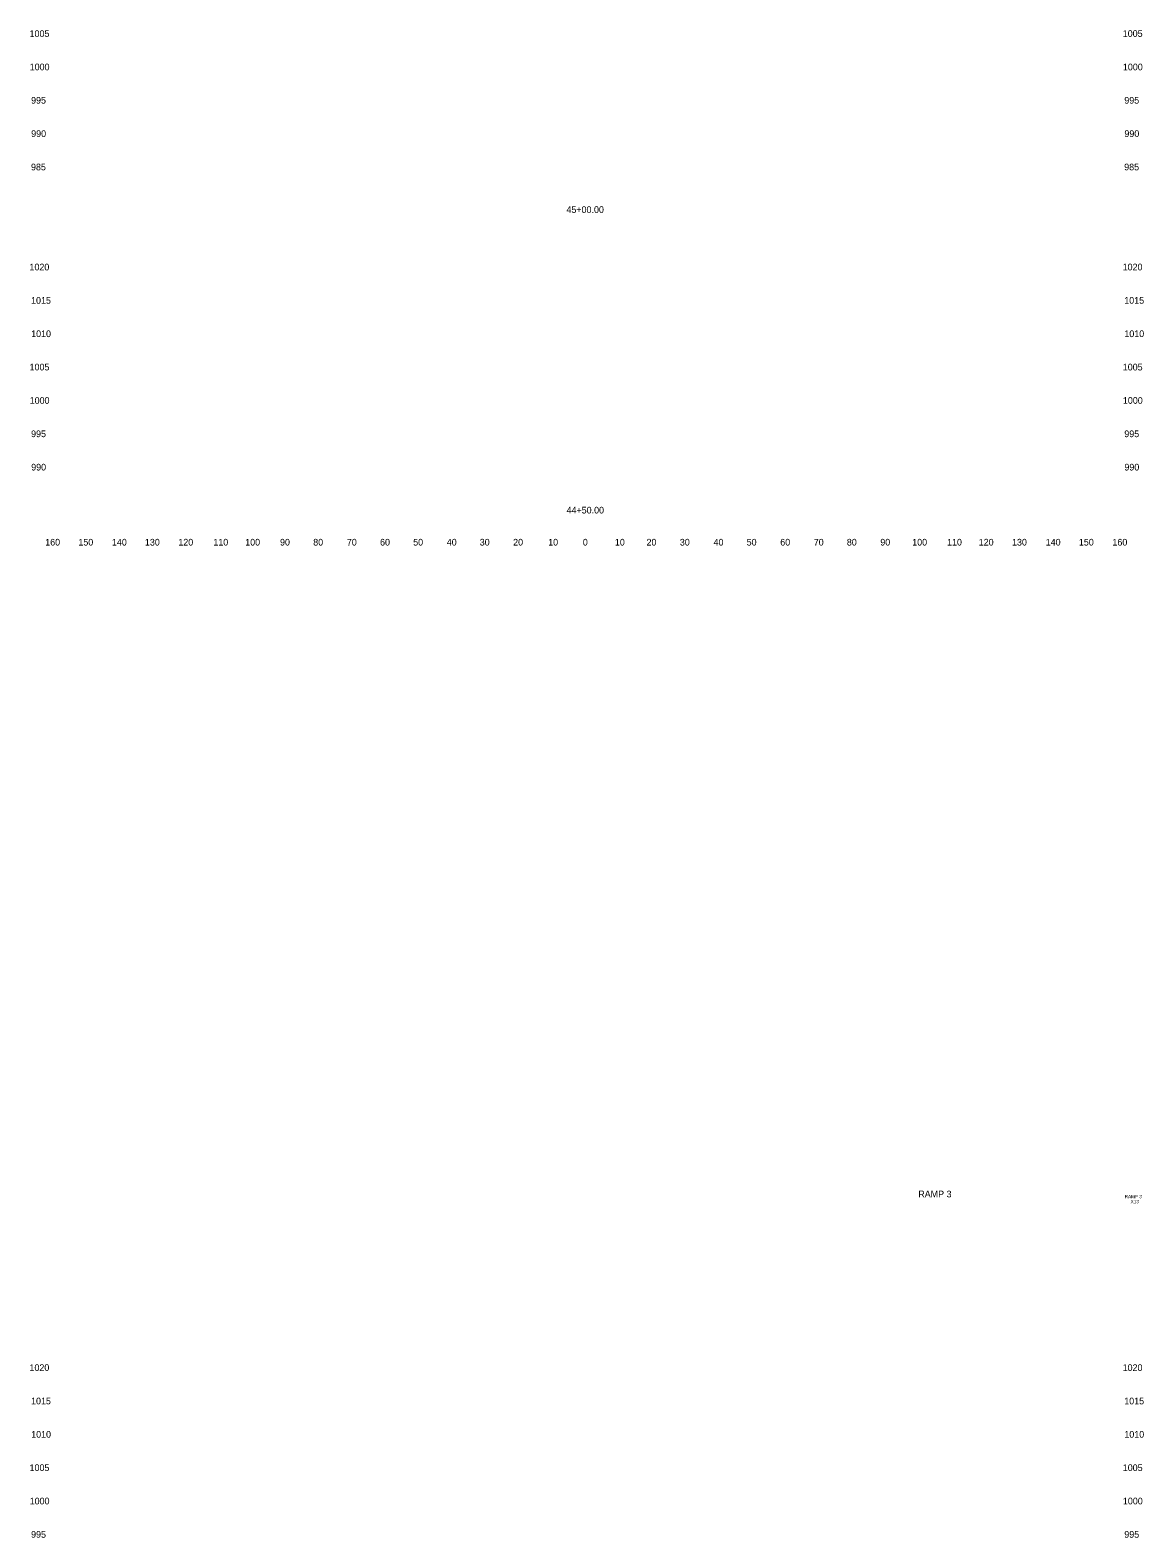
# Model space of a CAD drawing. Extents: x 4994 to 5843, y 4997 to 8804.
# Drawn here: x 5508.6 to 5842.5, y 5900 to 6352 of the extents above; entities that cross this region are included whole.
import ezdxf

# ---------------------------------------------------------------- set-up
doc = ezdxf.new("R2010")
doc.units = 0
for name, color, linetype in [('RD_SHT_ID', 7, 'Continuous'), ('RD_XS_TX_Offset', 7, 'Continuous'), ('RD_XS_TX_Station', 7, 'Continuous')]:
    doc.layers.add(name, color=color, linetype=linetype)

msp = doc.modelspace()

# ---------------------------------------------------------------- texts
at = {"layer": 'RD_SHT_ID'}
for s, height, p in [('RAMP 3', 2, (5774.89, 6002.06)), ('RAMP 3', 1, (5836.78, 6001.8)), ('X13', 1, (5838.57, 6000.3))]:
    msp.add_text(s, height=height, dxfattribs=at).set_placement(p)
at = {"layer": 'RD_XS_TX_Offset'}
for s, p in [('1005', (5508.4, 6350)), ('1005', (5836.2, 6350)), ('1000', (5508.44, 6340)), ('1000', (5836.24, 6340)), ('995', (5508.86, 6330)), ('995', (5836.66, 6330)), ('990', (5508.89, 6320)), ('990', (5836.69, 6320)), ('985', (5508.83, 6310)), ('985', (5836.63, 6310)), ('1020', (5508.37, 6280)), ('1020', (5836.17, 6280)), ('1015', (5508.85, 6270)), ('1015', (5836.65, 6270)), ('1010', (5508.88, 6260)), ('1010', (5836.68, 6260)), ('1005', (5508.4, 6250)), ('1005', (5836.2, 6250)), ('1000', (5508.44, 6240)), ('1000', (5836.24, 6240)), ('995', (5508.86, 6230)), ('995', (5836.66, 6230)), ('990', (5508.89, 6220)), ('990', (5836.69, 6220)), ('160', (5513.1, 6197.5)), ('150', (5523.04, 6197.5)), ('140', (5533.1, 6197.5)), ('130', (5542.99, 6197.5)), ('120', (5553.01, 6197.5)), ('110', (5563.51, 6197.5)), ('100', (5573.07, 6197.5)), ('90', (5583.5, 6197.5)), ('80', (5593.46, 6197.5)), ('70', (5603.54, 6197.5)), ('60', (5613.5, 6197.5)), ('50', (5623.43, 6197.5)), ('40', (5633.5, 6197.5)), ('30', (5643.39, 6197.5)), ('20', (5653.4, 6197.5)), ('10', (5663.91, 6197.5)), ('0', (5674.3, 6197.5)), ('0', (5674.3, 6197.5)), ('10', (5683.91, 6197.5)), ('20', (5693.4, 6197.5)), ('30', (5703.39, 6197.5)), ('40', (5713.5, 6197.5)), ('50', (5723.43, 6197.5)), ('60', (5733.5, 6197.5)), ('70', (5743.54, 6197.5)), ('80', (5753.46, 6197.5)), ('90', (5763.5, 6197.5)), ('100', (5773.07, 6197.5)), ('110', (5783.51, 6197.5)), ('120', (5793.01, 6197.5)), ('130', (5802.99, 6197.5)), ('140', (5813.1, 6197.5)), ('150', (5823.04, 6197.5)), ('160', (5833.1, 6197.5)), ('1020', (5508.37, 5950)), ('1020', (5836.17, 5950)), ('1015', (5508.85, 5940)), ('1015', (5836.65, 5940)), ('1010', (5508.88, 5930)), ('1010', (5836.68, 5930)), ('1005', (5508.4, 5920)), ('1005', (5836.2, 5920)), ('1000', (5508.44, 5910)), ('1000', (5836.24, 5910)), ('995', (5508.86, 5900)), ('995', (5836.66, 5900))]:
    msp.add_text(s, height=2, dxfattribs=at).set_placement(p)
at = {"layer": 'RD_XS_TX_Station'}
for s, p in [('45+00.00', (5669.39, 6297.23)), ('44+50.00', (5669.42, 6207.11))]:
    msp.add_text(s, height=2, dxfattribs=at).set_placement(p)

doc.saveas('drawing.dxf')
